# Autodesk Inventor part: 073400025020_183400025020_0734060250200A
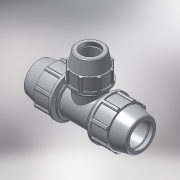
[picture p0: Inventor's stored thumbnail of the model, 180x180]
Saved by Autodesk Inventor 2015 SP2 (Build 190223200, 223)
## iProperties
Created: 2017-02
Part Number: 073400025020_183400025020_0734060250200A
Material: PVC-Piping
Description: PLASSON REDUCING TEE 25-20-25
Document SubType Name: Modeling
Designer: KIM
Mass: 92.6774 g
Surface Area: 199.44 cm^2
Volume: 66.1981 cm^3
Density: 1.4 g/cm^3
Appearance: Smooth - White
Author: Кирилл
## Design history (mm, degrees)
derived "07340.ipt"
feature "Solid1::07340.ipt"
feature "Solid2::07340.ipt"
tag "TaggingFeature1"
body "Solid1"
other parameters: "d2" = 25, "d4" = 6.25, "d5" = 21, "d7" = 54, "d11" = 2.5, "d13" = 120 deg, "d14" = 37.5, "d15" = 12 deg, "d16" = 46.98, "d18" = 1.25, "d19" = 35 deg, "d20" = 17.5 deg, "d21" = 50.22, "d23" = 0, "d25" = 360 deg, "d27" = 1.08, "d33" = 0.5, "d42" = 27, "d43" = 1.62, "d46" = 0.75, "d67" = 40.5, "d77" = 48, "d78" = 12 deg, "d79" = 74, "d80" = 120 deg, "d82" = 6.16667, "d87" = 2.46667, "d89" = 18.5, "d90" = 22.2, "d96" = 12.5, "d98" = 44.64, "d99" = 35 deg, "d100" = 17.5 deg, "d102" = 0, "d103" = 0.96, "d107" = 360 deg, "d109" = 0.6, "d112" = 1, "d113" = 3.2, "d114" = 0, "d118" = 41.76, "d126" = 22.5, "d127" = 58, "d131" = 2.96, "d132" = 18, "d133" = 57, "d135" = 0, "d138" = 3, "d143" = 0, "d148" = 36, "d168" = 22.5, "d170" = 0, "d173" = 0, "d175" = 0, "d176" = 3.2, "d177" = 0, "d_" = 25, "E_" = 54, "A_" = 74, "l_" = 58, "E_1" = 48, "l_1" = 57
